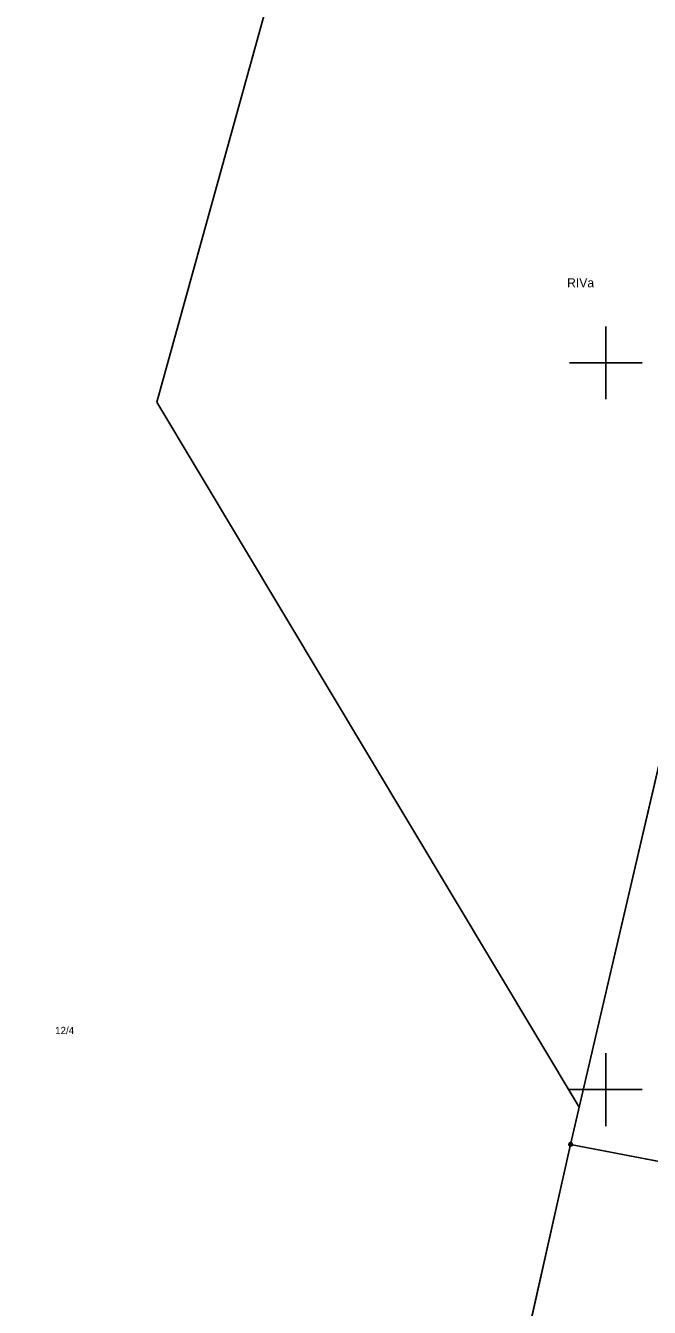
# Model space of a CAD drawing. Extents: x 6424617 to 6425697, y 5665845 to 5667190.
# Drawn here: x 6424820.1 to 6424906, y 5666570.1 to 5666746.4 of the extents above; entities that cross this region are included whole.
import ezdxf

# ---------------------------------------------------------------- set-up
doc = ezdxf.new("R2010")
doc.units = 0
for name, color, linetype in [('Warstwa 1', 7, 'Continuous'), ('Warstwa 10', 7, 'Continuous'), ('Warstwa 15', 7, 'Continuous'), ('Warstwa 2', 7, 'Continuous'), ('Warstwa 6', 7, 'Continuous'), ('Warstwa 63', 7, 'Continuous')]:
    doc.layers.add(name, color=color, linetype=linetype)

msp = doc.modelspace()

# ---------------------------------------------------------------- linework, layer by layer
at = {"layer": 'Warstwa 1'}
for p, q in [((6424838.22, 5666694.57), (6424899.64, 5666916.12)), ((6424838.22, 5666694.57), (6424899.64, 5666916.12)), ((6424896.34, 5666597.57), (6424930.46, 5666744.03)), ((6424896.34, 5666597.57), (6424930.46, 5666744.03)), ((6424838.22, 5666694.57), (6424896.34, 5666597.57)), ((6424838.22, 5666694.57), (6424896.34, 5666597.57)), ((6424895.16, 5666592.47), (6424896.34, 5666597.57)), ((6424895.16, 5666592.47), (6424896.34, 5666597.57)), ((6424863.57, 5666452.24), (6424895.16, 5666592.47)), ((6424863.57, 5666452.24), (6424895.16, 5666592.47)), ((6424895.16, 5666592.47), (6424928.89, 5666586.01)), ((6424895.16, 5666592.47), (6424928.89, 5666586.01))]:
    msp.add_line(p, q, dxfattribs=at)
at = {"layer": 'Warstwa 10'}
msp.add_circle((6424895.16, 5666592.47), 0.25, dxfattribs=at)
at = {"layer": 'Warstwa 6'}
msp.add_lwpolyline([(6424716.45, 5666344.63), (6424730.04, 5666344.35), (6424778.08, 5666337.65), (6424835.21, 5666326.25), (6424863.57, 5666452.24), (6424895.16, 5666592.47), (6424930.46, 5666744.03), (6424963.64, 5666736.21), (6424996.49, 5666728.81), (6425001.61, 5666749.86), (6425004.59, 5666768.33), (6425004.27, 5666802.33), (6425009.8, 5666830.19), (6425016.63, 5666870.23), (6425020.01, 5666882.89), (6425015.31, 5666889.08), (6425007.51, 5666895.23), (6424957.01, 5666906.7), (6424920.8, 5666746.62), (6424867.64, 5666760.89), (6424902.78, 5666916.32), (6424874.44, 5666914.51), (6424858.5, 5666915.71), (6424844.87, 5666917.42)], dxfattribs=at)
for points in [[(6424963.64, 5666736.21), (6424930.46, 5666744.03), (6424895.16, 5666592.47), (6424928.89, 5666586.01), (6424960.37, 5666579.88), (6424996.49, 5666728.81)], [(6424835.21, 5666326.25), (6424854.22, 5666322.77), (6424872.34, 5666313.51), (6424890.18, 5666301.67), (6424901.94, 5666342.13), (6424903.49, 5666349.42), (6424940.64, 5666499.33), (6424960.37, 5666579.88), (6424928.89, 5666586.01), (6424895.16, 5666592.47), (6424863.57, 5666452.24)]]:
    msp.add_lwpolyline(points, close=True, dxfattribs=at)
at = {"layer": 'Warstwa 63'}
for p, q in [((6424900, 5666705), (6424900, 5666695)), ((6424905, 5666700), (6424895, 5666700)), ((6424900, 5666605), (6424900, 5666595)), ((6424905, 5666600), (6424895, 5666600))]:
    msp.add_line(p, q, dxfattribs=at)

# ---------------------------------------------------------------- texts
at = {"layer": 'Warstwa 15'}
msp.add_text('12/4', height=1, dxfattribs=at).set_placement((6424824.21, 5666607.64))
at = {"layer": 'Warstwa 2'}
msp.add_text('RIVa', height=1.25, dxfattribs=at).set_placement((6424894.68, 5666710.37))

doc.saveas('drawing.dxf')
